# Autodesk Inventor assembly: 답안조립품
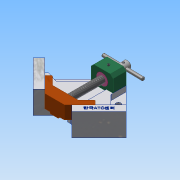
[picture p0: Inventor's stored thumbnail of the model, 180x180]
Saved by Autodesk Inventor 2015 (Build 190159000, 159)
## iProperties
Created: 2019-04
Part Number: 답안조립품
Document SubType Name: Assembly
Designer: user
Author: user
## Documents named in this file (10)
- C:\Users\user\Desktop\490407V1020\답안조립품.iam
- C:\Users\user\Desktop\490407V1020\본체.ipt
- C:\Users\user\Desktop\490407V1020\조.ipt
- C:\Users\user\Desktop\490407V1020\평행 핀 2.5x24.ipt
- C:\Users\user\Desktop\490407V1020\부시.ipt
- C:\Users\user\Desktop\490407V1020\핸들.ipt
- C:\Users\user\Desktop\490407V1020\리드스크류.ipt
- C:\Users\user\Desktop\490407V1020\서포트.ipt
- C:\Users\user\Desktop\490407V1020\멈춤나사 M4x5.ipt
- C:\Users\user\Desktop\490407V1020\멈춤나사 M4x10.ipt
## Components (1 placed, 1 different names)
1. 핸들:1
